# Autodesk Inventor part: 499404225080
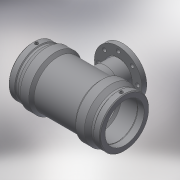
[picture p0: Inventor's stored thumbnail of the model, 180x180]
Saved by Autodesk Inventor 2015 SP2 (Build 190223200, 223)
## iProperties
Created: 2017-06
Part Number: 499404225080
Material: Generic
Description: PLASSON FLANGED TEE 225x80x225
Document SubType Name: Modeling
Designer: KIM
Mass: 57.3761 g
Surface Area: 241.06 cm^2
Volume: 57.3761 cm^3
Density: 1 g/cm^3
Appearance: Default
Author: KIM
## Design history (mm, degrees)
derived "499404.ipt"
feature "Solid1::499404.ipt"
tag "TaggingFeature1"
body "Solid1"
other parameters: "d13" = 494, "d14" = 17.6296, "d17" = 202.5, "d18" = 225, "d19" = 3.52592, "d20" = 168 deg, "d22" = 272.49, "d23" = 293, "d24" = 264.3153, "d25" = 135 deg, "d26" = 345.8, "d27" = 135 deg, "d35" = 15, "d39" = 5 deg, "d45" = 4, "d46" = 14, "d47" = 0, "d48" = -255, "d55" = 263.7, "d56" = 293, "d57" = 172.9, "d58" = 135 deg, "d59" = 122, "d60" = 122, "d61" = 135 deg, "d62" = 255, "d72" = 224.77, "d73" = 112.385, "d74" = -255, "d84" = 255, "d87" = 138, "d89" = 96, "d91" = 15 deg, "d92" = 104, "d95" = 4.14, "d97" = 18, "d100" = 0, "d102" = 360 deg, "d105" = 0, "d107" = 0, "d108" = 3, "d109" = 0, "d110" = 36.6, "d111" = 12.2, "d_" = 225, "L_" = 494, "L_1" = 122, "D_" = 293, "d_2" = 12, "H_" = 255, "d_1" = 138, "s_" = 18
